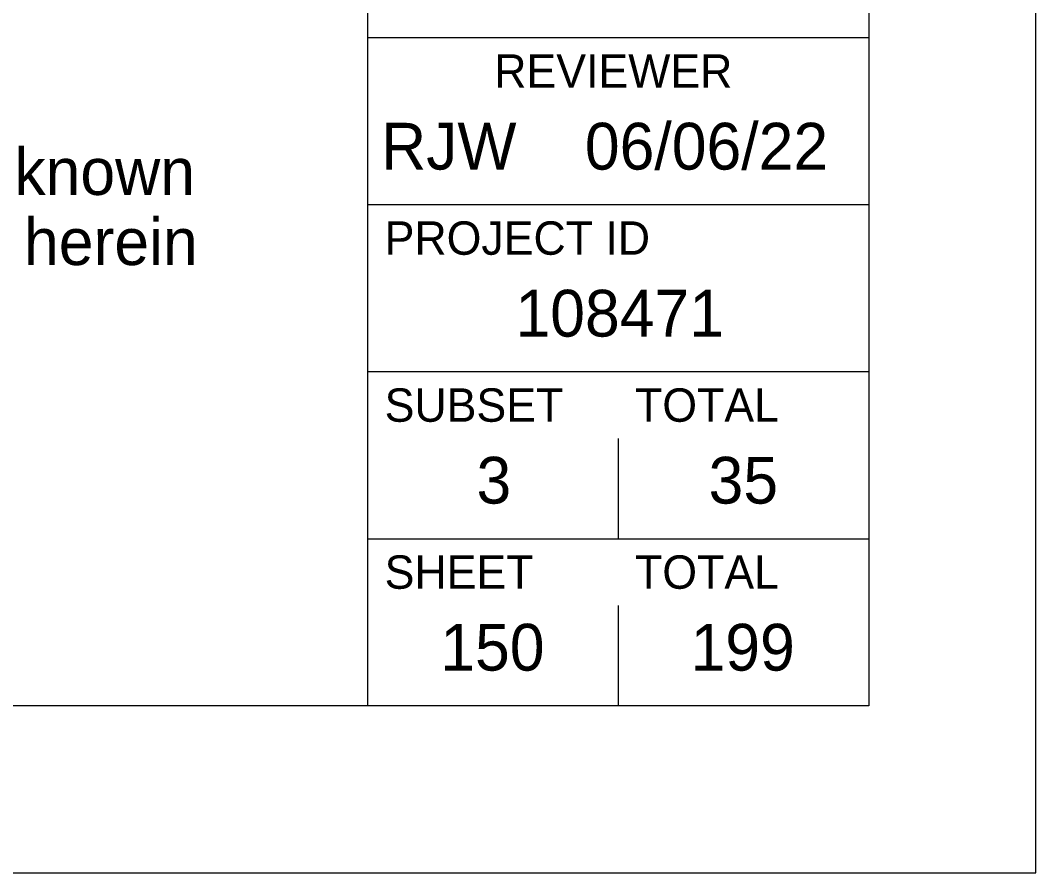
# Model space of a CAD drawing. Extents: x -0.2 to 34, y 0 to 22.
# Drawn here: x 30.959 to 34, y 0 to 2.552 of the extents above; entities that cross this region are included whole.
import ezdxf

# ---------------------------------------------------------------- set-up
doc = ezdxf.new("R2010")
doc.units = 0
for name, color, linetype in [('SH_Border', 7, 'Continuous'), ('SH_Cut_Line', 7, 'Continuous'), ('SH_Data', 7, 'Continuous'), ('SH_Text', 7, 'Continuous')]:
    doc.layers.add(name, color=color, linetype=linetype)

msp = doc.modelspace()

# ---------------------------------------------------------------- linework, layer by layer
at = {"layer": 'SH_Border'}
for p, q in [((32, 0.5), (32, 21.5)), ((32, 2.5), (33.5, 2.5)), ((32, 2), (33.5, 2)), ((32, 1.5), (33.5, 1.5)), ((32, 1), (33.5, 1))]:
    msp.add_line(p, q, dxfattribs=at)
msp.add_lwpolyline([(1.5, 21.5), (33.5, 21.5), (33.5, 0.5), (1.5, 0.5)], close=True, dxfattribs=at)
at = {"layer": 'SH_Cut_Line'}
msp.add_lwpolyline([(0, 0), (34, 0), (34, 22), (0, 22)], close=True, dxfattribs=at)
at = {"layer": 'SH_Data'}
for p, q in [((32.75, 1), (32.75, 1.3)), ((32.75, 0.5), (32.75, 0.8)), ((32.375, 0.675), (32.375, 0.675))]:
    msp.add_line(p, q, dxfattribs=at)

# ---------------------------------------------------------------- texts
for s, height, p in [('REVIEWER', 0.1, (32.3783, 2.35)), ('06/06/22', 0.14, (32.6497, 2.105)), ('RJW', 0.14, (32.0393, 2.105)), ('PROJECT ID', 0.1, (32.05, 1.85)), ('108471', 0.14, (32.4418, 1.605)), ('SUBSET', 0.1, (32.05, 1.35)), ('TOTAL', 0.1, (32.8, 1.35)), ('3', 0.14, (32.3251, 1.105)), ('35', 0.14, (33.0202, 1.105)), ('SHEET', 0.1, (32.05, 0.85)), ('TOTAL', 0.1, (32.8, 0.85)), ('150', 0.14, (32.2166, 0.605)), ('199', 0.14, (32.9662, 0.605))]:
    msp.add_text(s, height=height, dxfattribs=at).set_placement(p)
at = {"layer": 'SH_Text'}
for s, p in [('All of my work contained herein was conducted in accordance with Ohio Administrative Code 4733-37 commonly known', (21.5652, 2.0292)), ('as "A Minimum Standards for Boundary Surveys in the State of Ohio" unless noted.  The words I and my as used herein', (21.5652, 1.8192))]:
    msp.add_text(s, height=0.14, dxfattribs=at).set_placement(p)

doc.saveas('drawing.dxf')
